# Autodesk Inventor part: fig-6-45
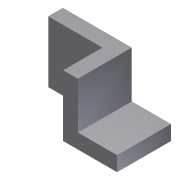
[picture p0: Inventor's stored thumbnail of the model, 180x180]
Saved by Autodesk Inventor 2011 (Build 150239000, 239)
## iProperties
Shininess: 77.0
Angle Display Precision: 2
Document Length Units: 11269
Document Angle Units: 11279
Document Time Units: 11290
Document Mass Units: 11283
Document Length Units Precision: 3
Document Angle Units Precision: 2
Created: 2001-12
Part Number: fig-6-45
Document SubType Name: Modeling
Designer: Renu Muthoo
Density: 1 g/cm^3
Density: 0.0
Volumn: 0.0
Area: 0.0
PropertySet Name: Model Information
Control State: 0
Master: False
Checked Out: False
Author: Renu Muthoo
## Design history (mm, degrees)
node "Sketch1"
sketch "Sketch2"
  geometry: L1 (16.794, 27.142)-(16.794, -22.858); L2 (16.794, -22.858)-(-27.206, -22.858); L3 (-27.206, -22.858)-(-27.206, -10.858); L4 (-27.206, -10.858)-(4.794, -10.858); L5 (4.794, -10.858)-(4.794, 27.142); L6 (4.794, 27.142)-(16.794, 27.142)
  constraints: 12 end point, 4 parallel, 2 perpendicular, 1 vertical
  dimensions: "d0" = 44 distance of L1.end L2.end; "d1" = 50 distance of L1.start L1.end; "d2" = 12 distance of L2.end L3.end
extrude "Extrusion1" new body sketch "Sketch2" distance "d3" = 44; taper "d4" = 0 deg
sketch "Sketch4"
  geometry: L1 (-16.794, -27.142)-(-16.794, 22.858) reference; L2 (27.206, 22.858)-(27.206, 10.858) reference; L3 (-16.794, -27.142)-(-61.001, -27.142); L4 (-61.001, -27.142)-(-61.001, 22.858); L5 (-61.001, 22.858)-(-16.794, 22.858)
  constraints: 6 end point, 2 perpendicular, 1 parallel
extrude "Extrusion3" join sketch "Sketch4" distance "d13" = 12; taper "d14" = 0 deg
body "Solid1"
